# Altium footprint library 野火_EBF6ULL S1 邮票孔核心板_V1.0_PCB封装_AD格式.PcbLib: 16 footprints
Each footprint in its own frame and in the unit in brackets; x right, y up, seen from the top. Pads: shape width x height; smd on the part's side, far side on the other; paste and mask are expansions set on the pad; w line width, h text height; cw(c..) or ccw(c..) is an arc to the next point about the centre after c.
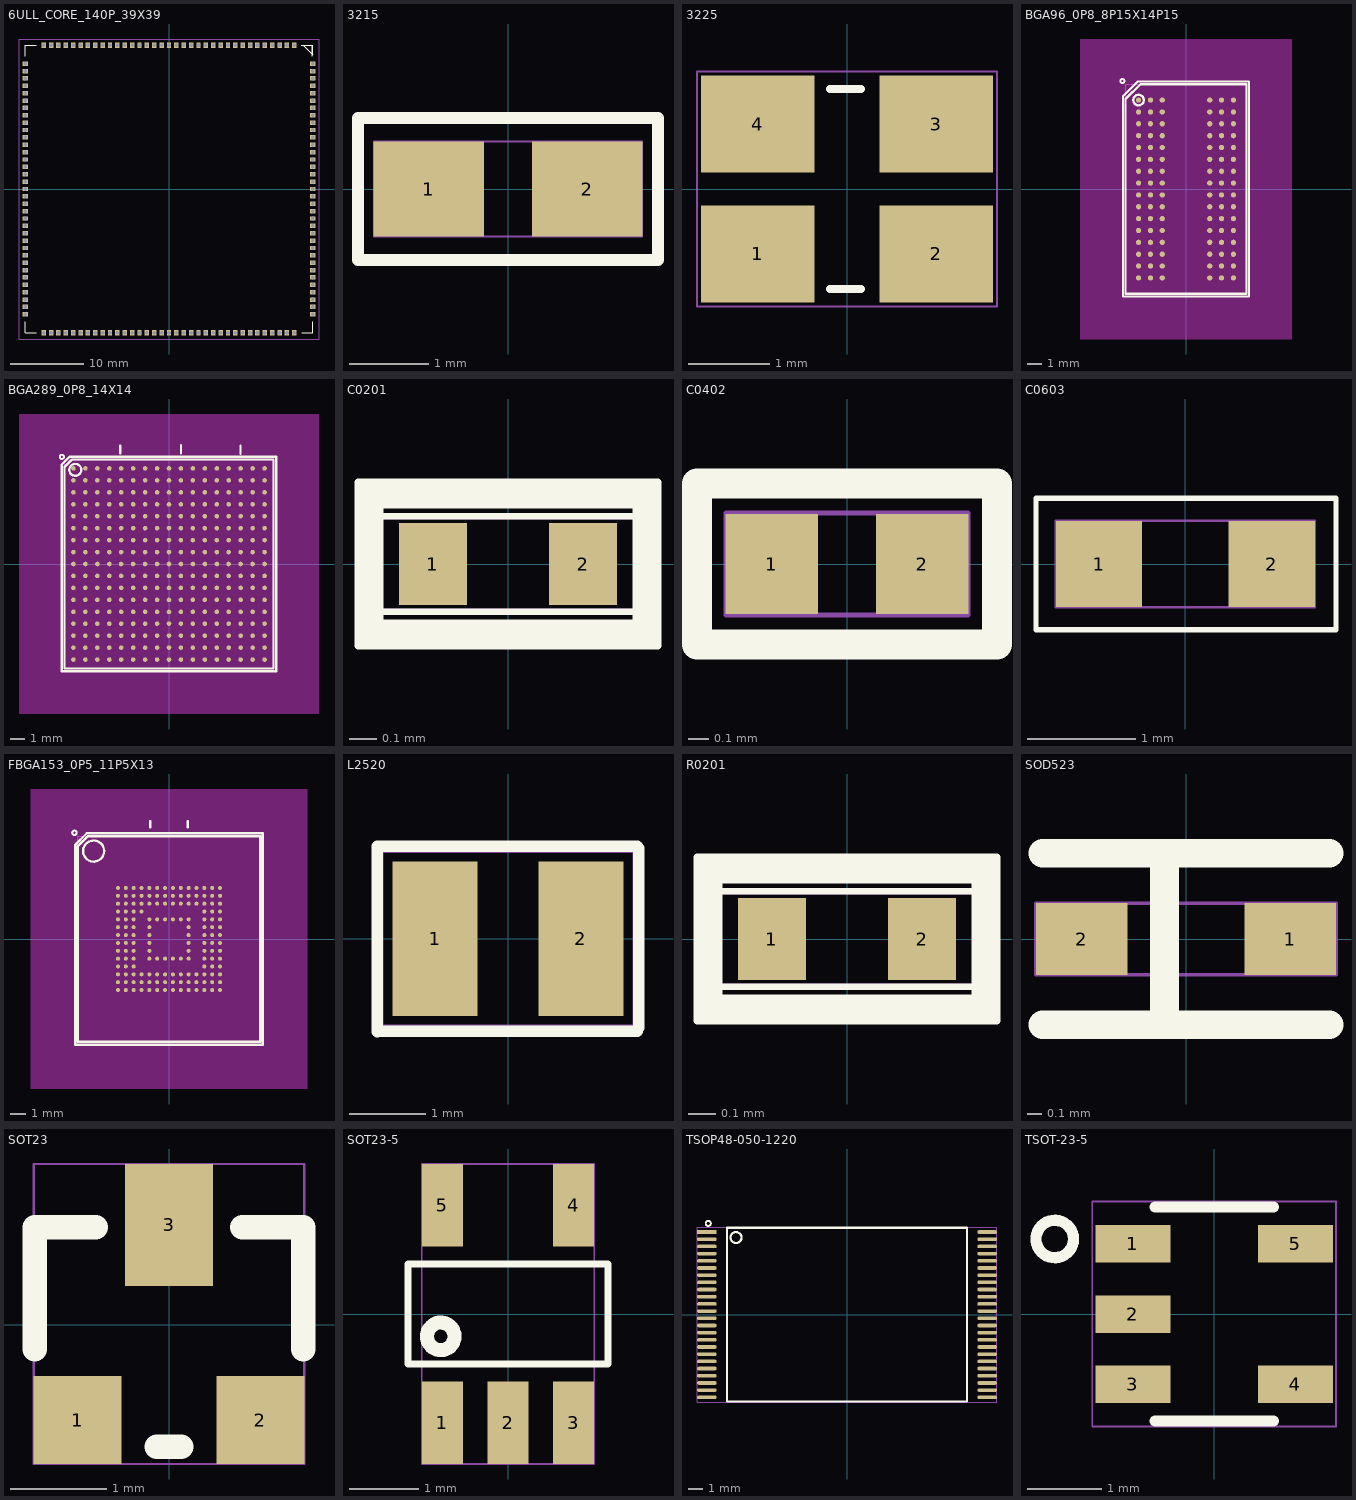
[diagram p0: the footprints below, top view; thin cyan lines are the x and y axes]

## 6ULL_CORE_140P_39X39 [mil]
pads (140):
  rect 23.62x31.5 / inner rect 23.62x31.5 / far side rect 23.62x78.74 hole 19.69 mask+1.97: 1(669.29,767.72) 2(629.92,767.72) 3(590.55,767.72) 4(551.18,767.72) 5(511.81,767.72) 6(472.44,767.72) 7(433.07,767.72) 8(393.7,767.72) 9(354.33,767.72) 10(314.96,767.72) 11(275.59,767.72) 12(236.22,767.72) 13(196.85,767.72) 14(157.48,767.72) 15(118.11,767.72) 16(78.74,767.72) 17(39.37,767.72) 18(0,767.72) 19(-39.37,767.72) 20(-78.74,767.72) 21(-118.11,767.72) 22(-157.48,767.72) 23(-196.85,767.72) 24(-236.22,767.72) 25(-275.59,767.72) 26(-314.96,767.72) 27(-354.33,767.72) 28(-393.7,767.72) 29(-433.07,767.72) 30(-472.44,767.72) 31(-511.81,767.72) 32(-551.18,767.72) 33(-590.55,767.72) 34(-629.92,767.72) 35(-669.29,767.72) 71(-669.29,-767.72) 72(-629.92,-767.72) 73(-590.55,-767.72) 74(-551.18,-767.72) 75(-511.81,-767.72) 76(-472.44,-767.72) 77(-433.07,-767.72) 78(-393.7,-767.72) 79(-354.33,-767.72) 80(-314.96,-767.72) 81(-275.59,-767.72) 82(-236.22,-767.72) 83(-196.85,-767.72) 84(-157.48,-767.72) 85(-118.11,-767.72) 86(-78.74,-767.72) 87(-39.37,-767.72) 88(0,-767.72) 89(39.37,-767.72) 90(78.74,-767.72) 91(118.11,-767.72) 92(157.48,-767.72) 93(196.85,-767.72) 94(236.22,-767.72) 95(275.59,-767.72) 96(314.96,-767.72) 97(354.33,-767.72) 98(393.7,-767.72) 99(433.07,-767.72) 100(472.44,-767.72) 101(511.81,-767.72) 102(551.18,-767.72) 103(590.55,-767.72) 104(629.92,-767.72) 105(669.29,-767.72)
  rect 31.5x23.62 / inner rect 31.5x23.62 / far side rect 78.74x23.62 hole 19.69 mask+1.97: 36(-767.72,669.29) 37(-767.72,629.92) 38(-767.72,590.55) 39(-767.72,551.18) 40(-767.72,511.81) 41(-767.72,472.44) 42(-767.72,433.07) 43(-767.72,393.7) 44(-767.72,354.33) 45(-767.72,314.96) 46(-767.72,275.59) 47(-767.72,236.22) 48(-767.72,196.85) 49(-767.72,157.48) 50(-767.72,118.11) 51(-767.72,78.74) 52(-767.72,39.37) 53(-767.72,0) 54(-767.72,-39.37) 55(-767.72,-78.74) 56(-767.72,-118.11) 57(-767.72,-157.48) 58(-767.72,-196.85) 59(-767.72,-236.22) 60(-767.72,-275.59) 61(-767.72,-314.96) 62(-767.72,-354.33) 63(-767.72,-393.7) 64(-767.72,-433.07) 65(-767.72,-472.44) 66(-767.72,-511.81) 67(-767.72,-551.18) 68(-767.72,-590.55) 69(-767.72,-629.92) 70(-767.72,-669.29) 106(767.72,-669.29) 107(767.72,-629.92) 108(767.72,-590.55) 109(767.72,-551.18) 110(767.72,-511.81) 111(767.72,-472.44) 112(767.72,-433.07) 113(767.72,-393.7) 114(767.72,-354.33) 115(767.72,-314.96) 116(767.72,-275.59) 117(767.72,-236.22) 118(767.72,-196.85) 119(767.72,-157.48) 120(767.72,-118.11) 121(767.72,-78.74) 122(767.72,-39.37) 123(767.72,0) 124(767.72,39.37) 125(767.72,78.74) 126(767.72,118.11) 127(767.72,157.48) 128(767.72,196.85) 129(767.72,236.22) 130(767.72,275.59) 131(767.72,314.96) 132(767.72,354.33) 133(767.72,393.7) 134(767.72,433.07) 135(767.72,472.44) 136(767.72,511.81) 137(767.72,551.18) 138(767.72,590.55) 139(767.72,629.92) 140(767.72,669.29)
Top Overlay:
  lines w1: 717.72,767.72 767.72,717.72 767.72,767.72 717.72,767.72
  lines w6: -767.72,-767.72 -708.66,-767.52 -767.72,-767.72 ; -767.72,-767.72 -767.72,-708.46 -767.72,-767.72 ; -767.72,767.72 -767.72,708.46 -767.72,767.72 ; -767.72,767.72 -708.66,767.52 -767.72,767.72 ; 765.43,767.17 765.43,707.91 765.43,767.17 ; 765.43,767.17 706.38,766.97 765.43,767.17 ; 767.72,-767.72 708.66,-767.52 767.72,-767.72 ; 767.72,-767.72 767.72,-708.46 767.72,-767.72
Top Assembly:
  text "J1" at -24.29,-25 h50
Mechanical 14:
  lines w1: -801.19,-801.19 801.19,-801.19 801.19,801.19 -801.19,801.19 -801.19,-801.19

## 3215 [mil]
pads (2):
  rect 55.1x47.2 smd mask+2: 1(-39.4,0) 2(39.4,0)
Top Overlay:
  lines w5.9: -74.8,-35.4 74.8,-35.4 74.8,35.4 -74.8,35.4 -74.8,-35.4
Top Assembly:
  text "Y2" at 38.93,25 h50
Mechanical 14:
  lines w1: -66.9,-23.6 -66.9,23.6 66.9,23.6 66.9,-23.6 -66.9,-23.6

## 3225 [mil]
pads (4):
  rect 55.1x47.2 smd mask+2: 1(-43.3,-31.5) 2(43.3,-31.5) 3(43.3,31.5) 4(-43.3,31.5)
Top Overlay:
  lines w3.9: -8.3,-48.5 6.7,-48.5 ; -8.3,48.5 6.7,48.5
Top Assembly:
  text "Y1" at -28.21,-25 h50
Mechanical 14:
  lines w1: -72.8,-57.1 72.8,-57.1 72.8,57.1 -72.8,57.1 -72.8,-57.1

## BGA96_0P8_8P15X14P15 [mil]
height 47
pads (96):
  round 14 smd mask+2: A1(-125.98,236.22) A2(-94.49,236.22) A3(-62.99,236.22) A7(62.99,236.22) A8(94.49,236.22) A9(125.98,236.22) B1(-125.98,204.72) B2(-94.49,204.72) B3(-62.99,204.72) B7(62.99,204.72) B8(94.49,204.72) B9(125.98,204.72) C1(-125.98,173.23) C2(-94.49,173.23) C3(-62.99,173.23) C7(62.99,173.23) C8(94.49,173.23) C9(125.98,173.23) D1(-125.98,141.73) D2(-94.49,141.73) D3(-62.99,141.73) D7(62.99,141.73) D8(94.49,141.73) D9(125.98,141.73) E1(-125.98,110.24) E2(-94.49,110.24) E3(-62.99,110.24) E7(62.99,110.24) E8(94.49,110.24) E9(125.98,110.24) F1(-125.98,78.74) F2(-94.49,78.74) F3(-62.99,78.74) F7(62.99,78.74) F8(94.49,78.74) F9(125.98,78.74) G1(-125.98,47.24) G2(-94.49,47.24) G3(-62.99,47.24) G7(62.99,47.24) G8(94.49,47.24) G9(125.98,47.24) H1(-125.98,15.75) H2(-94.49,15.75) H3(-62.99,15.75) H7(62.99,15.75) H8(94.49,15.75) H9(125.98,15.75) J1(-125.98,-15.75) J2(-94.49,-15.75) J3(-62.99,-15.75) J7(62.99,-15.75) J8(94.49,-15.75) J9(125.98,-15.75) K1(-125.98,-47.24) K2(-94.49,-47.24) K3(-62.99,-47.24) K7(62.99,-47.24) K8(94.49,-47.24) K9(125.98,-47.24) L1(-125.98,-78.74) L2(-94.49,-78.74) L3(-62.99,-78.74) L7(62.99,-78.74) L8(94.49,-78.74) L9(125.98,-78.74) M1(-125.98,-110.24) M2(-94.49,-110.24) M3(-62.99,-110.24) M7(62.99,-110.24) M8(94.49,-110.24) M9(125.98,-110.24) N1(-125.98,-141.73) N2(-94.49,-141.73) N3(-62.99,-141.73) N7(62.99,-141.73) N8(94.49,-141.73) N9(125.98,-141.73) P1(-125.98,-173.23) P2(-94.49,-173.23) P3(-62.99,-173.23) P7(62.99,-173.23) P8(94.49,-173.23) P9(125.98,-173.23) R1(-125.98,-204.72) R2(-94.49,-204.72) R3(-62.99,-204.72) R7(62.99,-204.72) R8(94.49,-204.72) R9(125.98,-204.72) T1(-125.98,-236.22) T2(-94.49,-236.22) T3(-62.99,-236.22) T7(62.99,-236.22) T8(94.49,-236.22) T9(125.98,-236.22)
Top Layer keep-out:
  region: -280.43,-398.54 280.43,-398.54 280.43,398.54 -280.43,398.54
Top Overlay:
  circle w5: c-169,287 r5.57
  circle w6: c-125.98,236.22 r14.08
  lines w6: -167.43,-285.55 -167.43,246.18 -128.07,285.54 167.43,285.54 167.43,-285.54 -167.43,-285.54 ; -160.43,-278.54 160.43,-278.54 160.43,278.54 -121.06,278.54 -160.43,239.17 -160.43,-278.54
Top Assembly:
  text "U3" at 40.23,25 h50
Mechanical 14:
  lines w1: -160.43,-278.54 160.43,-278.54 160.43,278.54 -160.43,278.54 -160.43,-278.54

## BGA289_0P8_14X14 [mil]
height 53
pads (289):
  round 12 smd mask+2: A1(-252,252) A2(-220.5,252) A3(-189,252) A4(-157.5,252) A5(-126,252) A6(-94.5,252) A7(-63,252) A8(-31.5,252) A9(0,252) A10(31.5,252) A11(63,252) A12(94.5,252) A13(126,252) A14(157.5,252) A15(189,252) A16(220.5,252) A17(252,252) B1(-252,220.5) B2(-220.5,220.5) B3(-189,220.5) B4(-157.5,220.5) B5(-126,220.5) B6(-94.5,220.5) B7(-63,220.5) B8(-31.5,220.5) B9(0,220.5) B10(31.5,220.5) B11(63,220.5) B12(94.5,220.5) B13(126,220.5) B14(157.5,220.5) B15(189,220.5) B16(220.5,220.5) B17(252,220.5) C1(-252,189) C2(-220.5,189) C3(-189,189) C4(-157.5,189) C5(-126,189) C6(-94.5,189) C7(-63,189) C8(-31.5,189) C9(0,189) C10(31.5,189) C11(63,189) C12(94.5,189) C13(126,189) C14(157.5,189) C15(189,189) C16(220.5,189) C17(252,189) D1(-252,157.5) D2(-220.5,157.5) D3(-189,157.5) D4(-157.5,157.5) D5(-126,157.5) D6(-94.5,157.5) D7(-63,157.5) D8(-31.5,157.5) D9(0,157.5) D10(31.5,157.5) D11(63,157.5) D12(94.5,157.5) D13(126,157.5) D14(157.5,157.5) D15(189,157.5) D16(220.5,157.5) D17(252,157.5) E1(-252,126) E2(-220.5,126) E3(-189,126) E4(-157.5,126) E5(-126,126) E6(-94.5,126) E7(-63,126) E8(-31.5,126) E9(0,126) E10(31.5,126) E11(63,126) E12(94.5,126) E13(126,126) E14(157.5,126) E15(189,126) E16(220.5,126) E17(252,126) F1(-252,94.5) F2(-220.5,94.5) F3(-189,94.5) F4(-157.5,94.5) F5(-126,94.5) F6(-94.5,94.5) F7(-63,94.5) F8(-31.5,94.5) F9(0,94.5) F10(31.5,94.5) F11(63,94.5) F12(94.5,94.5) F13(126,94.5) F14(157.5,94.5) F15(189,94.5) F16(220.5,94.5) F17(252,94.5) G1(-252,63) G2(-220.5,63) G3(-189,63) G4(-157.5,63) G5(-126,63) G6(-94.5,63) G7(-63,63) G8(-31.5,63) G9(0,63) G10(31.5,63) G11(63,63) G12(94.5,63) G13(126,63) G14(157.5,63) G15(189,63) G16(220.5,63) G17(252,63) H1(-252,31.5) H2(-220.5,31.5) H3(-189,31.5) H4(-157.5,31.5) H5(-126,31.5) H6(-94.5,31.5) H7(-63,31.5) H8(-31.5,31.5) H9(0,31.5) H10(31.5,31.5) H11(63,31.5) H12(94.5,31.5) H13(126,31.5) H14(157.5,31.5) H15(189,31.5) H16(220.5,31.5) H17(252,31.5) J1(-252,0) J2(-220.5,0) J3(-189,0) J4(-157.5,0) J5(-126,0) J6(-94.5,0) J7(-63,0) J8(-31.5,0) J9(0,0) J10(31.5,0) J11(63,0) J12(94.5,0) J13(126,0) J14(157.5,0) J15(189,0) J16(220.5,0) J17(252,0) K1(-252,-31.5) K2(-220.5,-31.5) K3(-189,-31.5) K4(-157.5,-31.5) K5(-126,-31.5) K6(-94.5,-31.5) K7(-63,-31.5) K8(-31.5,-31.5) K9(0,-31.5) K10(31.5,-31.5) K11(63,-31.5) K12(94.5,-31.5) K13(126,-31.5) K14(157.5,-31.5) K15(189,-31.5) K16(220.5,-31.5) K17(252,-31.5) L1(-252,-63) L2(-220.5,-63) L3(-189,-63) L4(-157.5,-63) L5(-126,-63) L6(-94.5,-63) L7(-63,-63) L8(-31.5,-63) L9(0,-63) L10(31.5,-63) L11(63,-63) L12(94.5,-63) L13(126,-63) L14(157.5,-63) L15(189,-63) L16(220.5,-63) L17(252,-63) M1(-252,-94.5) M2(-220.5,-94.5) M3(-189,-94.5) M4(-157.5,-94.5) M5(-126,-94.5) M6(-94.5,-94.5) M7(-63,-94.5) M8(-31.5,-94.5) M9(0,-94.5) M10(31.5,-94.5) M11(63,-94.5) M12(94.5,-94.5) M13(126,-94.5) M14(157.5,-94.5) M15(189,-94.5) M16(220.5,-94.5) M17(252,-94.5) N1(-252,-126) N2(-220.5,-126) N3(-189,-126) N4(-157.5,-126) N5(-126,-126) N6(-94.5,-126) N7(-63,-126) N8(-31.5,-126) N9(0,-126) N10(31.5,-126) N11(63,-126) N12(94.5,-126) N13(126,-126) N14(157.5,-126) N15(189,-126) N16(220.5,-126) N17(252,-126) P1(-252,-157.5) P2(-220.5,-157.5) P3(-189,-157.5) P4(-157.5,-157.5) P5(-126,-157.5) P6(-94.5,-157.5) P7(-63,-157.5) P8(-31.5,-157.5) P9(0,-157.5) P10(31.5,-157.5) P11(63,-157.5) P12(94.5,-157.5) P13(126,-157.5) P14(157.5,-157.5) P15(189,-157.5) P16(220.5,-157.5) P17(252,-157.5) R1(-252,-189) R2(-220.5,-189) R3(-189,-189) R4(-157.5,-189) R5(-126,-189) R6(-94.5,-189) R7(-63,-189) R8(-31.5,-189) R9(0,-189) R10(31.5,-189) R11(63,-189) R12(94.5,-189) R13(126,-189) R14(157.5,-189) R15(189,-189) R16(220.5,-189) R17(252,-189) T1(-252,-220.5) T2(-220.5,-220.5) T3(-189,-220.5) T4(-157.5,-220.5) T5(-126,-220.5) T6(-94.5,-220.5) T7(-63,-220.5) T8(-31.5,-220.5) T9(0,-220.5) T10(31.5,-220.5) T11(63,-220.5) T12(94.5,-220.5) T13(126,-220.5) T14(157.5,-220.5) T15(189,-220.5) T16(220.5,-220.5) T17(252,-220.5) U1(-252,-252) U2(-220.5,-252) U3(-189,-252) U4(-157.5,-252) U5(-126,-252) U6(-94.5,-252) U7(-63,-252) U8(-31.5,-252) U9(0,-252) U10(31.5,-252) U11(63,-252) U12(94.5,-252) U13(126,-252) U14(157.5,-252) U15(189,-252) U16(220.5,-252) U17(252,-252)
Top Layer keep-out:
  region: -395.6,-395.6 395.6,-395.6 395.6,395.6 -395.6,395.6
Top Overlay:
  circle w5: c-282.6,282.6 r5.57
  circle w6: c-247.09,248.26 r15.69
  lines w6: 31.7,292 31.7,313.4 ; 31.7,292.4 31.7,313.7 ; 188.4,290.6 188.4,311.9 ; 188.4,291.3 188.4,312.6 ; -282.6,-282.6 -282.6,262.6 -262.6,282.6 282.6,282.6 282.6,-282.6 -282.6,-282.6 ; -275.6,-275.6 -275.6,255.6 -255.6,275.6 275.6,275.6 275.6,-275.6 -275.6,-275.6 ; -128.3,291.3 -128.3,312.6 -128.3,291.3
Bottom Overlay:
  lines w6: -128.3,291.1 -128.3,312.4 ; 31.7,292.4 31.7,313.7 ; 188.4,290.6 188.4,311.9
Top Assembly:
  text "U2" at -40.23,-25 h50
Mechanical 14:
  lines w1: -275.6,-275.6 275.6,-275.6 275.6,275.6 -275.6,275.6 -275.6,-275.6

## C0201 [mil]
pads (2):
  rect 9.84x11.81 smd mask+1.97: 1(-10.83,0) 2(10.83,0)
Top Overlay:
  lines w1: -21.65,-11.81 21.65,-11.81 21.65,11.81 -21.65,11.81 -21.65,-11.81 ; -18.7,-6.89 18.7,-6.89 18.7,6.89 -18.7,6.89 -18.7,-6.89
  lines w4: -20,-10 -20,10 20,10 20,-10 -20,-10
Top Assembly:
  text "C99" at -62.61,-25 h50
Mechanical 14:
  lines w1: -18.7,-6.89 18.7,-6.89 18.7,6.89 -18.7,6.89 -18.7,-6.89

## C0402 [mil]
pads (2):
  rect 18.1x19.7 smd mask+1.95: 1(-14.8,0) 2(14.8,0)
Top Overlay:
  lines w5.9: -29.5,-15.8 -29.5,15.8 29.5,15.8 29.5,-15.8 -29.5,-15.8
Top Assembly:
  text "C95" at 63.8,25 h50
Mechanical 14:
  lines w1: -23.8,-10 23.8,-10 23.8,10 -23.8,10 -23.8,-10

## C0603 [mil]
pads (2):
  rect 31.5x31.5 smd mask+1.95: 1(-31.5,0) 2(31.5,0)
Top Overlay:
  lines w2: -54.5,-24 -54.5,24 55,24 55,-24 -54.5,-24
Top Assembly:
  text "C9" at -40.35,-25 h50
Mechanical 14:
  lines w1: -47.2,-15.8 47.2,-15.8 47.2,15.8 -47.2,15.8 -47.2,-15.8

## FBGA153_0P5_11P5X13 [mil]
height 47
pads (153):
  round 10 smd mask+1: A1(-127.95,127.95) A2(-108.27,127.95) A3(-88.58,127.95) A4(-68.9,127.95) A5(-49.21,127.95) A6(-29.53,127.95) A7(-9.84,127.95) A8(9.84,127.95) A9(29.53,127.95) A10(49.21,127.95) A11(68.9,127.95) A12(88.58,127.95) A13(108.27,127.95) A14(127.95,127.95) B1(-127.95,108.27) B2(-108.27,108.27) B3(-88.58,108.27) B4(-68.9,108.27) B5(-49.21,108.27) B6(-29.53,108.27) B7(-9.84,108.27) B8(9.84,108.27) B9(29.53,108.27) B10(49.21,108.27) B11(68.9,108.27) B12(88.58,108.27) B13(108.27,108.27) B14(127.95,108.27) C1(-127.95,88.58) C2(-108.27,88.58) C3(-88.58,88.58) C4(-68.9,88.58) C5(-49.21,88.58) C6(-29.53,88.58) C7(-9.84,88.58) C8(9.84,88.58) C9(29.53,88.58) C10(49.21,88.58) C11(68.9,88.58) C12(88.58,88.58) C13(108.27,88.58) C14(127.95,88.58) D1(-127.95,68.9) D2(-108.27,68.9) D3(-88.58,68.9) D4(-68.9,68.9) D12(88.58,68.9) D13(108.27,68.9) D14(127.95,68.9) E1(-127.95,49.21) E2(-108.27,49.21) E3(-88.58,49.21) E5(-49.21,49.21) E6(-29.53,49.21) E7(-9.84,49.21) E8(9.84,49.21) E9(29.53,49.21) E10(49.21,49.21) E12(88.58,49.21) E13(108.27,49.21) E14(127.95,49.21) F1(-127.95,29.53) F2(-108.27,29.53) F3(-88.58,29.53) F5(-49.21,29.53) F10(49.21,29.53) F12(88.58,29.53) F13(108.27,29.53) F14(127.95,29.53) G1(-127.95,9.84) G2(-108.27,9.84) G3(-88.58,9.84) G5(-49.21,9.84) G10(49.21,9.84) G12(88.58,9.84) G13(108.27,9.84) G14(127.95,9.84) H1(-127.95,-9.84) H2(-108.27,-9.84) H3(-88.58,-9.84) H5(-49.21,-9.84) H10(49.21,-9.84) H12(88.58,-9.84) H13(108.27,-9.84) H14(127.95,-9.84) J1(-127.95,-29.53) J2(-108.27,-29.53) J3(-88.58,-29.53) J5(-49.21,-29.53) J10(49.21,-29.53) J12(88.58,-29.53) J13(108.27,-29.53) J14(127.95,-29.53) K1(-127.95,-49.21) K2(-108.27,-49.21) K3(-88.58,-49.21) K5(-49.21,-49.21) K6(-29.53,-49.21) K7(-9.84,-49.21) K8(9.84,-49.21) K9(29.53,-49.21) K10(49.21,-49.21) K12(88.58,-49.21) K13(108.27,-49.21) K14(127.95,-49.21) L1(-127.95,-68.9) L2(-108.27,-68.9) L3(-88.58,-68.9) L12(88.58,-68.9) L13(108.27,-68.9) L14(127.95,-68.9) M1(-127.95,-88.58) M2(-108.27,-88.58) M3(-88.58,-88.58) M4(-68.9,-88.58) M5(-49.21,-88.58) M6(-29.53,-88.58) M7(-9.84,-88.58) M8(9.84,-88.58) M9(29.53,-88.58) M10(49.21,-88.58) M11(68.9,-88.58) M12(88.58,-88.58) M13(108.27,-88.58) M14(127.95,-88.58) N1(-127.95,-108.27) N2(-108.27,-108.27) N3(-88.58,-108.27) N4(-68.9,-108.27) N5(-49.21,-108.27) N6(-29.53,-108.27) N7(-9.84,-108.27) N8(9.84,-108.27) N9(29.53,-108.27) N10(49.21,-108.27) N11(68.9,-108.27) N12(88.58,-108.27) N13(108.27,-108.27) N14(127.95,-108.27) P1(-127.95,-127.95) P2(-108.27,-127.95) P3(-88.58,-127.95) P4(-68.9,-127.95) P5(-49.21,-127.95) P6(-29.53,-127.95) P7(-9.84,-127.95) P8(9.84,-127.95) P9(29.53,-127.95) P10(49.21,-127.95) P11(68.9,-127.95) P12(88.58,-127.95) P13(108.27,-127.95) P14(127.95,-127.95)
Top Layer keep-out:
  region: -346.46,-375.98 -346.46,375.98 346.46,375.98 346.46,-375.98
Top Overlay:
  circle w5: c-237,266 r5.57
  circle w6: c-188.98,220.47 r26.41
  lines w6: -235.35,-264.87 -235.35,235.77 -206.24,264.87 235.35,264.87 235.35,-264.87 -235.35,-264.87 ; -228.35,-257.87 -228.35,232.87 -203.35,257.87 228.35,257.87 228.35,-257.87 -228.35,-257.87 ; -47.24,279.53 -47.24,295.28 -47.24,279.53 ; 47.24,279.53 47.24,295.28 47.24,279.53
Bottom Overlay:
  lines w6: -47.24,279.53 -47.24,295.28 ; 47.24,279.53 47.24,295.28
Top Assembly:
  text "U4" at 41.42,25 h50
Mechanical 14:
  lines w1: -228.35,-257.87 228.35,-257.87 228.35,257.87 -228.35,257.87 -228.35,-257.87

## L2520 [mil]
height 47
pads (2):
  rect 44x80 smd mask+2: 1(-37.75,0) 2(37.75,0)
Top Overlay:
  lines w6: -67.68,47.92 67.09,47.92 ; -67.67,-48.15 -67.67,48.03 ; -65.71,-47.92 67.09,-47.92 ; 67.67,-46.06 67.67,46.97
Top Assembly:
  text "L2" at -33.69,-25 h50
Mechanical 14:
  lines w1: -65,-45 -65,45 65,45 65,-45 -65,-45

## R0201 [mil]
height 12
pads (2):
  rect 9.84x11.81 smd mask+1.97: 1(-10.83,0) 2(10.83,0)
Top Overlay:
  lines w1: -21.65,-11.81 21.65,-11.81 21.65,11.81 -21.65,11.81 -21.65,-11.81 ; -18.7,-6.89 18.7,-6.89 18.7,6.89 -18.7,6.89 -18.7,-6.89
  lines w4: -20,-10 -20,10 20,10 20,-10 -20,-10
Top Assembly:
  text "R9" at 37.73,25 h50
Mechanical 14:
  lines w1: -18.7,-6.89 18.7,-6.89 18.7,6.89 -18.7,6.89 -18.7,-6.89

## SOD523 [mil]
pads (2):
  rect 25.2x19.7 smd mask+1.95: 1(28.7,0) 2(-28.7,0)
Top Overlay:
  lines w7.9: -39.4,-23.6 39.4,-23.6 ; -39.4,23.6 39.4,23.6 ; -5.9,-22.6 -5.9,23.6
Top Assembly:
  text "D5" at 38.93,25 h50
Mechanical 14:
  lines w1: -41.3,-9.8 41.3,-9.8 41.3,9.8 -41.3,9.8 -41.3,-9.8

## SOT23 [mil]
pads (3):
  rect 36x36 smd mask+1.95: 1(-37.5,-39) 2(37.5,-39)
  rect 36x50 smd mask+1.95: 3(0,41)
Top Overlay:
  lines w10: -55,-10 -55,40 -30,40 ; -5,-50 5,-50 ; 30,40 55,40 55,-10
Top Assembly:
  text "U8" at -40.23,-25 h50
Mechanical 14:
  lines w1: -55.5,-57 55.5,-57 55.5,66 -55.5,66 -55.5,-57

## SOT23-5 [mil]
pads (5):
  rect 23.6x47.2 smd mask+2: 1(-37.4,-62.01) 2(0,-62.01) 3(37.4,-62.01) 4(37.4,62.01) 5(-37.4,62.01)
Top Overlay:
  circle w8: c-38.4,-12.79 r7.87
  lines w4: -57.09,-28.54 -57.09,18.7 -57.09,28.54 57.09,28.54 57.09,18.7 57.09,-28.54 -57.09,-28.54
Top Assembly:
  text "U9" at -39.04,-25 h50
Mechanical 14:
  lines w1: -49.21,-85.63 49.21,-85.63 49.21,85.63 -49.21,85.63 -49.21,-85.63

## TSOP48-050-1220 [mil]
pads (48):
  rect 54x10 smd mask+2: 1(-383.9,226.4)
  oval 54x10 smd mask+2: 2(-383.9,206.7) 3(-383.9,187) 4(-383.9,167.3) 5(-383.9,147.6) 6(-383.9,128) 7(-383.9,108.3) 8(-383.9,88.6) 9(-383.9,68.9) 10(-383.9,49.2) 11(-383.9,29.5) 12(-383.9,9.8) 13(-383.9,-9.8) 14(-383.9,-29.5) 15(-383.9,-49.2) 16(-383.9,-68.9) 17(-383.9,-88.6) 18(-383.9,-108.3) 19(-383.9,-128) 20(-383.9,-147.6) 21(-383.9,-167.3) 22(-383.9,-187) 23(-383.9,-206.7) 24(-383.9,-226.4) 25(383.9,-226.4) 26(383.9,-206.7) 27(383.9,-187) 28(383.9,-167.3) 29(383.9,-147.6) 30(383.9,-128) 31(383.9,-108.3) 32(383.9,-88.6) 33(383.9,-68.9) 34(383.9,-49.2) 35(383.9,-29.5) 36(383.9,-9.8) 37(383.9,9.8) 38(383.9,29.5) 39(383.9,49.2) 40(383.9,68.9) 41(383.9,88.6) 42(383.9,108.3) 43(383.9,128) 44(383.9,147.6) 45(383.9,167.3) 46(383.9,187) 47(383.9,206.7) 48(383.9,226.4)
Top Overlay:
  circle w6: c-303.86,211.38 r14.96
  circle w5: c-380,250 r7.1
  lines w6: -328.5,-238.2 328.7,-238.2 328.7,238.2 -328.5,238.2 -328.5,-238.2
Top Assembly:
  text "U5" at 40.23,25 h50
Mechanical 14:
  lines w1: -410,-240 -410,240 410,240 410,-240 -410,-240

## TSOT-23-5 [mil]
height 39
pads (5):
  rect 40x20 smd mask+2.5: 1(-43.31,37.4) 2(-43.31,0) 3(-43.31,-37.4) 4(43.31,-37.4) 5(43.31,37.4)
Top Overlay:
  circle w6: c-85,40 r10
  lines w6: -31.5,-57.09 31.5,-57.09 -31.5,-57.09 ; -31.5,57.09 31.5,57.09 -31.5,57.09
Top Assembly:
  text "U7" at 40.23,25 h50
Mechanical 14:
  lines w1: -65,-60 -65,60 65,60 65,-60 -65,-60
